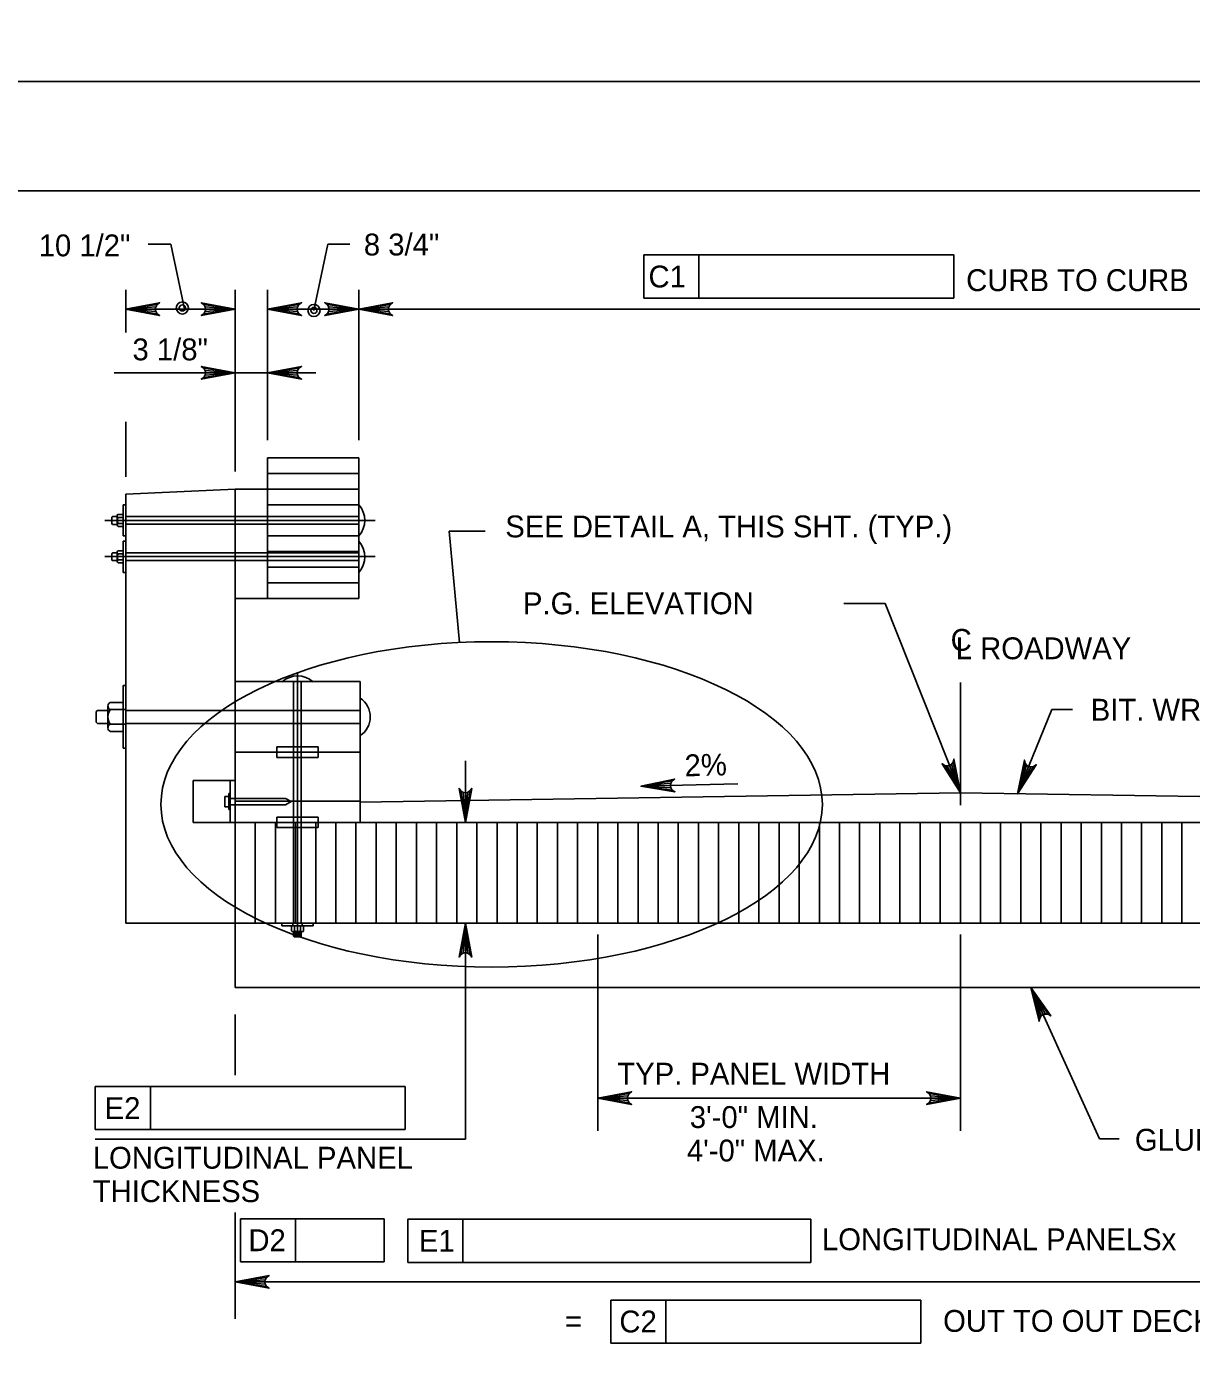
# Model space of a CAD drawing. Extents: x 638268 to 640277, y 295465 to 298435.
# Drawn here: x 638497.2 to 638656.9, y 296477.7 to 296661 of the extents above; entities that cross this region are included whole.
import ezdxf

# ---------------------------------------------------------------- set-up
doc = ezdxf.new("R2010")
doc.units = 0
for name, color, linetype in [('2', 7, 'Continuous'), ('3', 7, 'Continuous'), ('4', 7, 'Continuous'), ('7', 7, 'Continuous'), ('PLT-BNDY', 7, 'Continuous')]:
    doc.layers.add(name, color=color, linetype=linetype)

msp = doc.modelspace()

# ---------------------------------------------------------------- linework, layer by layer
at = {"layer": '2'}
for p, q in [((638475.46, 296638.46), (639261.46, 296638.46)), ((638530.22, 296582.51), (638530.22, 296601.79)), ((638530.22, 296601.79), (638542.72, 296601.79)), ((638542.72, 296582.51), (638542.72, 296601.79)), ((638530.22, 296599.66), (638542.72, 296599.66)), ((638525.77, 296597.52), (638510.76, 296596.82)), ((638510.76, 296537.97), (638510.76, 296596.82)), ((638525.77, 296597.52), (638530.22, 296597.52)), ((638525.77, 296597.52), (638525.77, 296571.1)), ((638530.22, 296597.52), (638542.72, 296597.52)), ((638510.43, 296591.09), (638510.43, 296595.37)), ((638510.43, 296595.37), (638510.76, 296595.37)), ((638542.72, 296595.37), (638530.22, 296595.37)), ((638508.84, 296593.67), (638508.93, 296593.75)), ((638508.84, 296593.67), (638508.84, 296592.77)), ((638509.57, 296593.75), (638508.93, 296593.75)), ((638509.57, 296593.84), (638509.57, 296592.6)), ((638509.57, 296593.84), (638509.57, 296592.6)), ((638509.71, 296594.05), (638510.43, 296594.05)), ((638509.71, 296593.63), (638510.43, 296593.63)), ((638510.43, 296592.39), (638510.43, 296594.05)), ((638542.72, 296593.77), (638510.76, 296593.77)), ((638508.84, 296592.77), (638508.93, 296592.67)), ((638509.57, 296592.67), (638508.93, 296592.67)), ((638509.71, 296592.81), (638510.43, 296592.81)), ((638509.71, 296592.39), (638510.43, 296592.39)), ((638510.76, 296591.09), (638510.43, 296591.09)), ((638510.43, 296591.09), (638510.43, 296591.09)), ((638542.72, 296592.7), (638510.76, 296592.7)), ((638510.76, 296591.09), (638510.76, 296591.09)), ((638542.72, 296591.09), (638530.22, 296591.09)), ((638510.43, 296586.08), (638510.43, 296590.36)), ((638510.43, 296590.36), (638510.76, 296590.36)), ((638508.84, 296588.68), (638508.93, 296588.76)), ((638508.84, 296588.68), (638508.84, 296587.78)), ((638508.84, 296587.78), (638508.93, 296587.7)), ((638509.57, 296588.76), (638508.93, 296588.76)), ((638509.57, 296587.7), (638508.93, 296587.7)), ((638509.57, 296588.83), (638509.57, 296587.59)), ((638509.57, 296588.83), (638509.57, 296587.59)), ((638509.71, 296589.04), (638510.43, 296589.04)), ((638509.71, 296588.62), (638510.43, 296588.62)), ((638509.71, 296587.8), (638510.43, 296587.8)), ((638509.71, 296587.39), (638510.43, 296587.39)), ((638510.43, 296587.39), (638510.43, 296589.04)), ((638542.72, 296588.76), (638510.76, 296588.76)), ((638542.72, 296587.7), (638510.76, 296587.7)), ((638542.72, 296588.95), (638530.22, 296588.95)), ((638510.76, 296586.08), (638510.43, 296586.08)), ((638510.43, 296586.08), (638510.43, 296586.08)), ((638510.76, 296586.08), (638510.76, 296586.08)), ((638542.72, 296586.8), (638530.22, 296586.8)), ((638530.22, 296584.65), (638542.72, 296584.65)), ((638525.77, 296582.51), (638542.72, 296582.51)), ((638525.77, 296571.1), (638525.77, 296561.44)), ((638525.77, 296571.1), (638542.91, 296571.1)), ((638533.79, 296571.1), (638533.79, 296537.97)), ((638534.34, 296536.14), (638534.34, 296572.34)), ((638534.85, 296571.1), (638534.85, 296537.97)), ((638542.91, 296571.1), (638542.91, 296561.44)), ((638510.39, 296570.55), (638510.39, 296561.98)), ((638510.76, 296570.55), (638510.39, 296570.55)), ((638510.76, 296570.55), (638510.76, 296561.98)), ((638508.29, 296564.78), (638508.29, 296567.74)), ((638508.62, 296567.25), (638510.39, 296567.25)), ((638508.64, 296568.24), (638510.39, 296568.24)), ((638510.39, 296568.24), (638510.39, 296564.27)), ((638510.76, 296567.25), (638510.39, 296567.25)), ((638506.69, 296566.99), (638506.87, 296567.14)), ((638506.69, 296566.99), (638506.69, 296565.54)), ((638506.69, 296565.54), (638506.87, 296565.37)), ((638508.29, 296567.14), (638506.87, 296567.14)), ((638508.29, 296567.14), (638508.29, 296567.14)), ((638542.91, 296567.14), (638510.76, 296567.14)), ((638506.87, 296565.37), (638508.29, 296565.37)), ((638508.62, 296565.28), (638510.39, 296565.28)), ((638508.66, 296564.27), (638510.39, 296564.27)), ((638510.76, 296565.28), (638510.39, 296565.28)), ((638542.91, 296565.37), (638510.76, 296565.37)), ((638510.39, 296561.98), (638510.76, 296561.98)), ((638531.48, 296562.15), (638531.48, 296560.7)), ((638531.48, 296562.15), (638537.18, 296562.15)), ((638537.18, 296562.15), (638537.18, 296560.7)), ((638525.77, 296561.44), (638525.77, 296551.79)), ((638525.77, 296561.44), (638542.91, 296561.44)), ((638531.48, 296560.7), (638537.18, 296560.7)), ((638542.91, 296561.44), (638542.91, 296551.79)), ((638520.03, 296557.52), (638520.03, 296551.79)), ((638525.77, 296557.52), (638520.03, 296557.52)), ((638525.09, 296557.52), (638525.09, 296551.79)), ((638581.43, 296556.74), (638594.73, 296557.08)), ((638524.9, 296555.35), (638524.37, 296555.35)), ((638524.37, 296555.35), (638524.37, 296553.94)), ((638524.9, 296555.73), (638525.09, 296555.73)), ((638524.9, 296555.73), (638524.9, 296553.56)), ((638525.09, 296555.07), (638532.7, 296555.07)), ((638542.91, 296554.7), (638525.77, 296554.7)), ((638533.47, 296554.64), (638532.7, 296555.07)), ((638533.47, 296554.64), (638532.7, 296554.18)), ((638524.9, 296553.94), (638524.37, 296553.94)), ((638524.9, 296553.56), (638525.09, 296553.56)), ((638525.09, 296554.18), (638532.7, 296554.18)), ((638520.03, 296551.79), (638525.77, 296551.79)), ((638525.77, 296551.79), (638525.77, 296544.72)), ((638531.48, 296552.51), (638531.48, 296551.08)), ((638531.48, 296552.51), (638537.18, 296552.51)), ((638531.48, 296551.08), (638537.18, 296551.08)), ((638537.18, 296552.51), (638537.18, 296551.08)), ((638532.17, 296537.97), (638532.17, 296537.97)), ((638532.17, 296537.97), (638532.17, 296537.61)), ((638533.68, 296537.97), (638533.68, 296537.61)), ((638534.96, 296537.97), (638534.96, 296537.61)), ((638536.47, 296537.61), (638536.47, 296537.97)), ((638532.17, 296537.66), (638532.17, 296537.66)), ((638532.17, 296537.61), (638536.47, 296537.61)), ((638533.51, 296536.92), (638533.51, 296537.61)), ((638534.96, 296536.79), (638533.72, 296536.79)), ((638533.79, 296536.79), (638533.79, 296536.15)), ((638533.87, 296536.06), (638533.79, 296536.15)), ((638533.87, 296536.7), (638534.77, 296536.7)), ((638533.87, 296536.61), (638534.77, 296536.61)), ((638533.87, 296536.51), (638534.77, 296536.51)), ((638533.87, 296536.42), (638534.77, 296536.42)), ((638533.87, 296536.34), (638534.77, 296536.34)), ((638533.87, 296536.23), (638534.77, 296536.23)), ((638533.87, 296536.15), (638534.77, 296536.15)), ((638534.77, 296536.06), (638533.87, 296536.06)), ((638533.93, 296536.92), (638533.93, 296537.61)), ((638534.75, 296536.92), (638534.75, 296537.61)), ((638534.77, 296536.06), (638534.85, 296536.15)), ((638534.85, 296536.79), (638534.85, 296536.15)), ((638535.16, 296536.92), (638535.16, 296537.61))]:
    msp.add_line(p, q, dxfattribs=at)
for centre, radius, start, end in [((638540.32, 296593.22), 3.23, 318.5212, 41.4788), ((638509.8, 296593.84), 0.228, 114.702, 244.7086), ((638510.28, 296593.22), 0.703, 144.5002, 216.0965), ((638509.8, 296592.6), 0.227, 114.1235, 245.2701), ((638540.32, 296588.22), 3.23, 318.5212, 41.4788), ((638509.8, 296588.84), 0.228, 114.702, 244.7086), ((638510.28, 296588.22), 0.703, 144.5002, 216.0965), ((638509.8, 296587.6), 0.227, 114.1235, 245.2701), ((638534.34, 296568.65), 3.23, 48.5212, 131.4788), ((638508.86, 296567.74), 0.545, 113.4078, 245.8697), ((638510, 296566.25), 1.69, 143.8906, 215.5087), ((638541.23, 296566.25), 3.07, 303.2799, 56.719), ((638508.86, 296564.77), 0.548, 115.2831, 249.0228), ((638533.72, 296537.01), 0.227, 204.7299, 335.8765), ((638534.34, 296537.49), 0.703, 233.9035, 305.4998), ((638534.96, 296537.01), 0.228, 205.2914, 335.298)]:
    msp.add_arc(centre, radius, start, end, dxfattribs=at)
at = {"layer": '3'}
for p, q in [((638525.77, 296597.52), (638525.77, 296544.72)), ((638544.98, 296593.22), (638507.88, 296593.22)), ((638544.98, 296588.25), (638507.88, 296588.25)), ((638542.91, 296554.56), (638625.28, 296555.82)), ((638625.28, 296555.82), (638707.66, 296554.56)), ((638525.77, 296537.97), (638525.77, 296551.79)), ((638724.8, 296551.79), (638525.77, 296551.79)), ((638510.76, 296537.97), (638525.77, 296537.97)), ((638525.77, 296529.11), (638525.77, 296537.97)), ((638525.77, 296537.97), (638724.8, 296537.97)), ((638724.8, 296529.11), (638525.77, 296529.11))]:
    msp.add_line(p, q, dxfattribs=at)
at = {"layer": '4'}
for p, q in [((638513.83, 296631.12), (638516.94, 296631.12)), ((638516.94, 296631.12), (638518.87, 296622.03)), ((638538.51, 296631.12), (638536.58, 296622.03)), ((638538.51, 296631.12), (638541.49, 296631.12)), ((638581.83, 296629.64), (638624.35, 296629.64)), ((638581.83, 296629.64), (638581.83, 296623.73)), ((638589.39, 296629.64), (638589.39, 296623.73)), ((638624.35, 296629.64), (638624.35, 296623.73)), ((638510.76, 296619), (638510.76, 296624.85)), ((638525.77, 296599.93), (638525.77, 296624.85)), ((638530.22, 296604.21), (638530.22, 296624.85)), ((638542.72, 296604.21), (638542.72, 296624.85)), ((638510.76, 296622.2), (638525.77, 296622.2)), ((638530.22, 296622.2), (638738.62, 296622.2)), ((638581.83, 296623.73), (638624.35, 296623.73)), ((638509.19, 296613.46), (638536.82, 296613.46)), ((638510.76, 296599.19), (638510.76, 296606.73)), ((638556.56, 296576.46), (638555.15, 296591.76)), ((638555.15, 296591.76), (638560.07, 296591.76)), ((638614.95, 296581.83), (638609.27, 296581.83)), ((638625.28, 296555.82), (638614.95, 296581.83)), ((638625.28, 296554.14), (638625.28, 296570.98)), ((638633.11, 296555.7), (638637.81, 296567.28)), ((638637.81, 296567.28), (638640.65, 296567.28)), ((638557.36, 296551.79), (638557.36, 296560.23)), ((638555.95, 296537.97), (638553.28, 296537.97)), ((638557.36, 296537.97), (638557.36, 296532.52)), ((638575.51, 296536.41), (638575.51, 296509.45)), ((638625.28, 296536.41), (638625.28, 296509.45)), ((638557.36, 296532.52), (638557.36, 296508.3)), ((638634.95, 296529.11), (638644.34, 296508.36)), ((638525.77, 296525.41), (638525.77, 296517.12)), ((638506.58, 296515.53), (638549.1, 296515.53)), ((638506.58, 296515.53), (638506.58, 296509.63)), ((638514.14, 296515.53), (638514.14, 296509.63)), ((638549.1, 296515.53), (638549.1, 296509.63)), ((638575.51, 296513.95), (638625.28, 296513.95)), ((638506.58, 296509.63), (638549.1, 296509.63)), ((638506.58, 296508.3), (638557.36, 296508.3)), ((638644.34, 296508.36), (638647.06, 296508.36)), ((638525.77, 296498.26), (638525.77, 296483.66)), ((638526.5, 296497.41), (638546.21, 296497.41)), ((638526.5, 296497.41), (638526.5, 296491.5)), ((638534.07, 296497.41), (638534.07, 296491.5)), ((638546.21, 296497.41), (638546.21, 296491.5)), ((638549.47, 296497.32), (638604.76, 296497.32)), ((638549.47, 296497.32), (638549.47, 296491.41)), ((638557.03, 296497.32), (638557.03, 296491.41)), ((638604.76, 296497.32), (638604.76, 296491.41)), ((638526.5, 296491.5), (638546.21, 296491.5)), ((638549.47, 296491.41), (638604.76, 296491.41)), ((638525.77, 296488.73), (638724.8, 296488.73)), ((638577.31, 296486.25), (638619.83, 296486.25)), ((638577.31, 296486.25), (638577.31, 296480.34)), ((638584.87, 296486.25), (638584.87, 296480.34)), ((638619.83, 296486.25), (638619.83, 296480.34)), ((638577.31, 296480.34), (638619.83, 296480.34))]:
    msp.add_line(p, q, dxfattribs=at)
for points in [[(638510.75, 296622.2), (638515.41, 296623.07), (638515.06, 296622.82), (638514.87, 296622.51), (638514.82, 296622.2), (638514.87, 296621.89), (638515.06, 296621.57), (638515.41, 296621.32), (638510.75, 296622.2), (638515.06, 296621.57), (638514.87, 296621.89), (638510.75, 296622.2), (638514.82, 296622.2), (638514.87, 296622.51), (638510.75, 296622.2), (638515.06, 296622.82)], [(638525.77, 296622.2), (638521.11, 296623.08), (638521.46, 296622.83), (638521.65, 296622.52), (638521.7, 296622.2), (638521.65, 296621.89), (638521.46, 296621.58), (638521.11, 296621.33), (638525.77, 296622.2), (638521.46, 296621.58), (638521.65, 296621.89), (638525.77, 296622.2), (638521.7, 296622.2), (638521.65, 296622.52), (638525.77, 296622.2), (638521.46, 296622.83)], [(638530.22, 296622.2), (638534.88, 296623.08), (638534.53, 296622.83), (638534.34, 296622.52), (638534.29, 296622.2), (638534.34, 296621.89), (638534.53, 296621.58), (638534.88, 296621.33), (638530.22, 296622.2), (638534.53, 296621.58), (638534.34, 296621.89), (638530.22, 296622.2), (638534.29, 296622.2), (638534.34, 296622.52), (638530.22, 296622.2), (638534.53, 296622.83)], [(638542.72, 296622.2), (638538.06, 296623.07), (638538.42, 296622.82), (638538.6, 296622.51), (638538.66, 296622.2), (638538.6, 296621.89), (638538.42, 296621.57), (638538.06, 296621.32), (638542.72, 296622.2), (638538.42, 296621.57), (638538.6, 296621.89), (638542.72, 296622.2), (638538.66, 296622.2), (638538.6, 296622.51), (638542.72, 296622.2), (638538.42, 296622.82)], [(638542.72, 296622.2), (638547.38, 296623.07), (638547.02, 296622.82), (638546.84, 296622.51), (638546.78, 296622.2), (638546.84, 296621.89), (638547.02, 296621.57), (638547.38, 296621.32), (638542.72, 296622.2), (638547.02, 296621.57), (638546.84, 296621.89), (638542.72, 296622.2), (638546.78, 296622.2), (638546.84, 296622.51), (638542.72, 296622.2), (638547.02, 296622.82)], [(638525.77, 296613.47), (638521.11, 296614.34), (638521.46, 296614.09), (638521.65, 296613.78), (638521.7, 296613.47), (638521.65, 296613.16), (638521.46, 296612.84), (638521.11, 296612.6), (638525.77, 296613.47), (638521.46, 296612.84), (638521.65, 296613.16), (638525.77, 296613.47), (638521.7, 296613.47), (638521.65, 296613.78), (638525.77, 296613.47), (638521.46, 296614.09)], [(638530.22, 296613.47), (638534.88, 296614.34), (638534.53, 296614.09), (638534.34, 296613.78), (638534.29, 296613.47), (638534.34, 296613.16), (638534.53, 296612.84), (638534.88, 296612.6), (638530.22, 296613.47), (638534.53, 296612.84), (638534.34, 296613.16), (638530.22, 296613.47), (638534.29, 296613.47), (638534.34, 296613.78), (638530.22, 296613.47), (638534.53, 296614.09)], [(638625.28, 296555.82), (638622.75, 296559.82), (638623.12, 296559.58), (638623.47, 296559.53), (638623.78, 296559.59), (638624.06, 296559.76), (638624.28, 296560.05), (638624.38, 296560.47), (638625.28, 296555.82), (638624.28, 296560.05), (638624.06, 296559.76), (638625.28, 296555.82), (638623.78, 296559.59), (638623.47, 296559.53), (638625.28, 296555.82), (638623.12, 296559.58)], [(638633.11, 296555.7), (638634.05, 296560.34), (638634.15, 296559.92), (638634.36, 296559.63), (638634.63, 296559.46), (638634.94, 296559.39), (638635.3, 296559.45), (638635.67, 296559.69), (638633.11, 296555.7), (638635.3, 296559.45), (638634.94, 296559.39), (638633.11, 296555.7), (638634.63, 296559.46), (638634.36, 296559.63), (638633.11, 296555.7), (638634.15, 296559.92)], [(638557.36, 296551.79), (638556.49, 296556.45), (638556.74, 296556.09), (638557.05, 296555.9), (638557.36, 296555.85), (638557.67, 296555.9), (638557.99, 296556.09), (638558.23, 296556.45), (638557.36, 296551.79), (638557.99, 296556.09), (638557.67, 296555.9), (638557.36, 296551.79), (638557.36, 296555.85), (638557.05, 296555.9), (638557.36, 296551.79), (638556.74, 296556.09)], [(638581.43, 296556.74), (638586.06, 296557.73), (638585.71, 296557.47), (638585.53, 296557.15), (638585.49, 296556.84), (638585.55, 296556.53), (638585.74, 296556.22), (638586.11, 296555.98), (638581.43, 296556.74), (638585.74, 296556.22), (638585.55, 296556.53), (638581.43, 296556.74), (638585.49, 296556.84), (638585.53, 296557.15), (638581.43, 296556.74), (638585.71, 296557.47)], [(638557.36, 296537.97), (638558.23, 296533.31), (638557.99, 296533.67), (638557.67, 296533.85), (638557.36, 296533.91), (638557.05, 296533.85), (638556.74, 296533.67), (638556.49, 296533.31), (638557.36, 296537.97), (638556.74, 296533.67), (638557.05, 296533.85), (638557.36, 296537.97), (638557.36, 296533.91), (638557.67, 296533.85), (638557.36, 296537.97), (638557.99, 296533.67)], [(638634.95, 296529.11), (638637.67, 296525.22), (638637.29, 296525.45), (638636.93, 296525.48), (638636.62, 296525.41), (638636.36, 296525.23), (638636.15, 296524.93), (638636.07, 296524.5), (638634.95, 296529.11), (638636.15, 296524.93), (638636.36, 296525.23), (638634.95, 296529.11), (638636.62, 296525.41), (638636.93, 296525.48), (638634.95, 296529.11), (638637.29, 296525.45)], [(638575.51, 296513.95), (638580.17, 296514.82), (638579.82, 296514.57), (638579.63, 296514.26), (638579.58, 296513.95), (638579.63, 296513.64), (638579.82, 296513.32), (638580.17, 296513.08), (638575.51, 296513.95), (638579.82, 296513.32), (638579.63, 296513.64), (638575.51, 296513.95), (638579.58, 296513.95), (638579.63, 296514.26), (638575.51, 296513.95), (638579.82, 296514.57)], [(638625.28, 296513.95), (638620.62, 296513.08), (638620.98, 296513.32), (638621.17, 296513.64), (638621.22, 296513.95), (638621.17, 296514.26), (638620.98, 296514.57), (638620.62, 296514.82), (638625.28, 296513.95), (638620.98, 296514.57), (638621.17, 296514.26), (638625.28, 296513.95), (638621.22, 296513.95), (638621.17, 296513.64), (638625.28, 296513.95), (638620.98, 296513.32)], [(638525.77, 296488.73), (638530.43, 296489.6), (638530.07, 296489.35), (638529.88, 296489.04), (638529.83, 296488.73), (638529.88, 296488.42), (638530.07, 296488.1), (638530.43, 296487.86), (638525.77, 296488.73), (638530.07, 296488.1), (638529.88, 296488.42), (638525.77, 296488.73), (638529.83, 296488.73), (638529.88, 296489.04), (638525.77, 296488.73), (638530.07, 296489.35)]]:
    msp.add_lwpolyline(points, dxfattribs=at)
for points in [[(638635.66, 296526.44), (638636.48, 296526.81), (638634.95, 296529.11)], [(638578.51, 296514.45), (638578.51, 296513.45), (638575.51, 296513.95)], [(638622.28, 296514.45), (638622.28, 296513.45), (638625.28, 296513.95)]]:
    msp.add_lwpolyline(points, close=True, dxfattribs=at)
for centre, radius in [((638518.53, 296622.37), 0.833), ((638518.53, 296622.37), 0.417), ((638536.58, 296622.03), 0.833), ((638536.58, 296622.03), 0.417)]:
    msp.add_circle(centre, radius, dxfattribs=at)
msp.add_ellipse((638560.96, 296554.25), major_axis=(45.37, 0), ratio=0.49188, dxfattribs=at)
at = {"layer": '7'}
for p, q in [((638528.53, 296537.97), (638528.53, 296551.79)), ((638531.29, 296537.97), (638531.29, 296551.79)), ((638534.06, 296537.97), (638534.06, 296551.79)), ((638536.82, 296537.97), (638536.82, 296551.79)), ((638539.58, 296537.97), (638539.58, 296551.79)), ((638542.35, 296537.97), (638542.35, 296551.79)), ((638545.11, 296537.97), (638545.11, 296551.79)), ((638547.88, 296537.97), (638547.88, 296551.79)), ((638550.64, 296537.97), (638550.64, 296551.79)), ((638553.4, 296537.97), (638553.4, 296551.79)), ((638556.17, 296537.97), (638556.17, 296551.79)), ((638558.93, 296537.97), (638558.93, 296551.79)), ((638561.7, 296537.97), (638561.7, 296551.79)), ((638564.46, 296537.97), (638564.46, 296551.79)), ((638567.22, 296537.97), (638567.22, 296551.79)), ((638569.99, 296537.97), (638569.99, 296551.79)), ((638572.75, 296537.97), (638572.75, 296551.79)), ((638575.52, 296551.79), (638575.52, 296537.97)), ((638578.28, 296537.97), (638578.28, 296551.79)), ((638581.04, 296537.97), (638581.04, 296551.79)), ((638583.81, 296537.97), (638583.81, 296551.79)), ((638586.57, 296537.97), (638586.57, 296551.79)), ((638589.33, 296537.97), (638589.33, 296551.79)), ((638592.1, 296537.97), (638592.1, 296551.79)), ((638594.86, 296537.97), (638594.86, 296551.79)), ((638597.62, 296537.97), (638597.62, 296551.79)), ((638600.39, 296537.97), (638600.39, 296551.79)), ((638603.15, 296537.97), (638603.15, 296551.79)), ((638605.92, 296537.97), (638605.92, 296551.79)), ((638608.68, 296537.97), (638608.68, 296551.79)), ((638611.44, 296537.97), (638611.44, 296551.79)), ((638614.21, 296537.97), (638614.21, 296551.79)), ((638616.97, 296537.97), (638616.97, 296551.79)), ((638619.73, 296537.97), (638619.73, 296551.79)), ((638622.5, 296537.97), (638622.5, 296551.79)), ((638625.28, 296551.79), (638625.28, 296537.97)), ((638628.02, 296537.97), (638628.02, 296551.79)), ((638630.79, 296537.97), (638630.79, 296551.79)), ((638633.55, 296537.97), (638633.55, 296551.79)), ((638636.32, 296537.97), (638636.32, 296551.79)), ((638639.08, 296537.97), (638639.08, 296551.79)), ((638641.85, 296537.97), (638641.85, 296551.79)), ((638644.61, 296537.97), (638644.61, 296551.79)), ((638647.37, 296537.97), (638647.37, 296551.79)), ((638650.13, 296537.97), (638650.13, 296551.79)), ((638652.9, 296537.97), (638652.9, 296551.79)), ((638655.66, 296537.97), (638655.66, 296551.79))]:
    msp.add_line(p, q, dxfattribs=at)
at = {"layer": 'PLT-BNDY'}
for points in [[(638435.46, 297247.46), (639276.46, 297247.46), (639276.46, 296653.46), (638435.46, 296653.46)], [(638435.46, 296653.46), (639276.46, 296653.46), (639276.46, 296059.46), (638435.46, 296059.46)]]:
    msp.add_lwpolyline(points, close=True, dxfattribs=at)

# ---------------------------------------------------------------- texts
at = {"layer": '4'}
for s, p in [('10 1/2"', (638498.82, 296629.45)), ('8 3/4"', (638543.43, 296629.57)), ('C1', (638582.48, 296625.18)), ('CURB TO CURB', (638626.06, 296624.68)), ('SEE DETAIL A, THIS SHT. (TYP.)', (638562.83, 296590.89)), ('P.G. ELEVATION', (638565.26, 296580.34)), ('C', (638623.93, 296575.32)), ('L ROADWAY', (638624.63, 296574.17)), ('BIT. WRG. SURFACE', (638643.15, 296565.74)), ('TYP. PANEL WIDTH', (638578.2, 296515.8)), ('E2', (638507.87, 296511.08)), ('3\'-0" MIN.', (638588.15, 296509.85)), ('GLULAM STIFFENER BEAM', (638649.2, 296506.73)), ('LONGITUDINAL PANEL', (638506.24, 296504.27)), ('4\'-0" MAX.', (638587.75, 296505.26)), ('THICKNESS', (638506.24, 296499.68)), ('D2', (638527.59, 296492.95)), ('E1', (638550.98, 296492.87)), ('LONGITUDINAL PANELSx', (638606.28, 296493.08)), ('C2', (638578.49, 296481.8)), ('OUT TO OUT DECK WIDTH', (638622.9, 296481.88)), ('=', (638571.03, 296481.88))]:
    msp.add_text(s, height=3, dxfattribs=at).set_placement(p)
for s, rotation, p in [('3 1/8"', 360, (638511.69, 296615.18)), ('2%', 1.5039, (638587.47, 296558.09))]:
    msp.add_text(s, height=3, rotation=rotation, dxfattribs=at).set_placement(p)

doc.saveas('drawing.dxf')
